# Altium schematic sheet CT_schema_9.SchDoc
size 287 x 160 mm
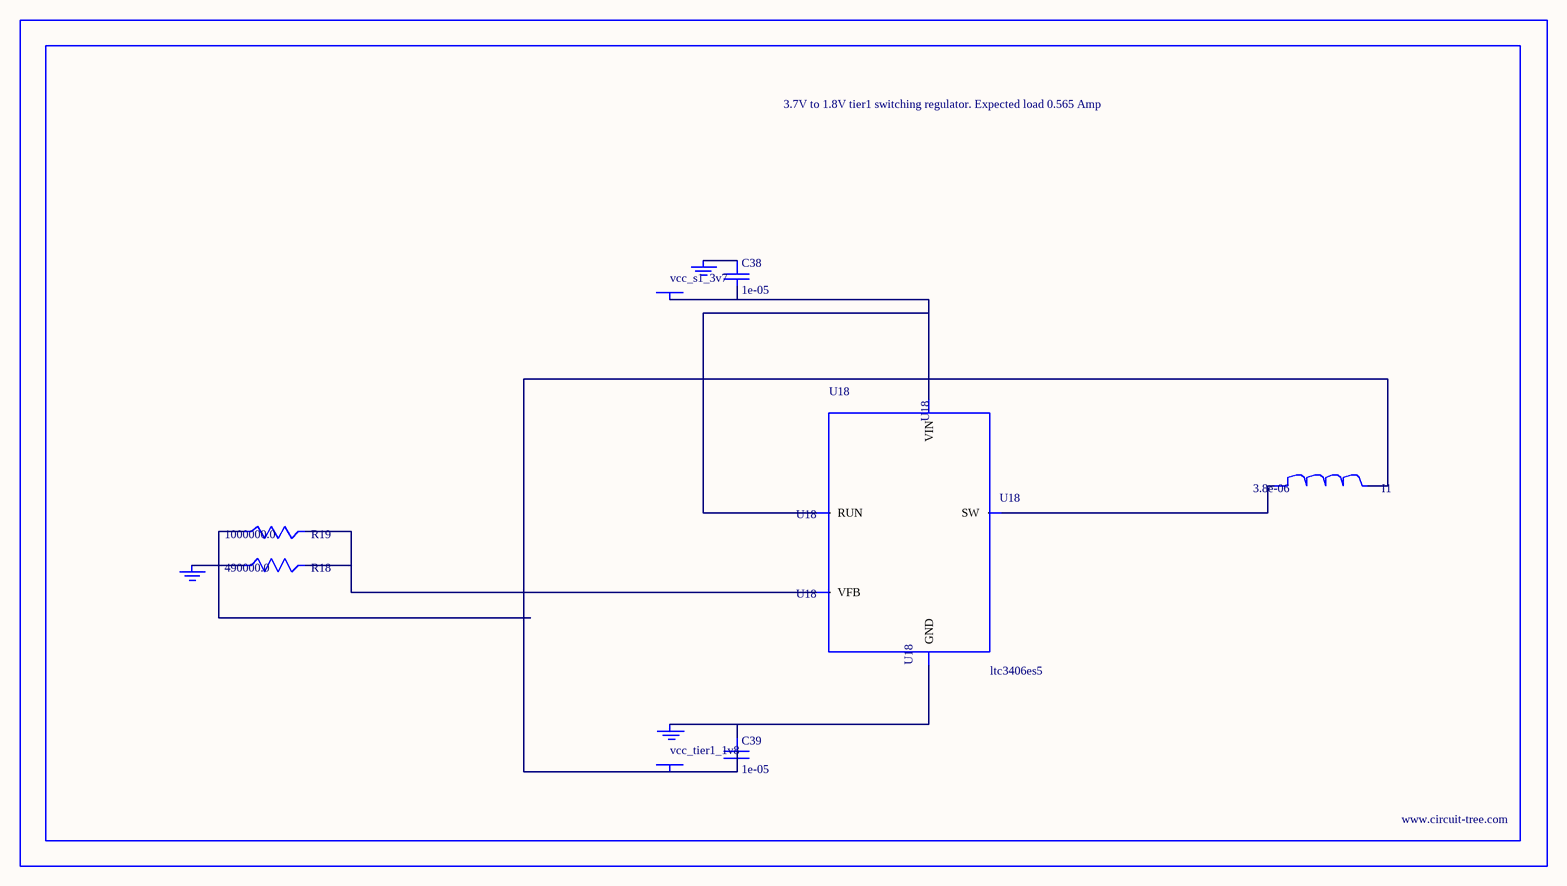
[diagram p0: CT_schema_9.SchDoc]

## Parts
BORDER8  (no value)
C38  1e-05  [C0805]
C39  1e-05  [C0805]
GND_INSTANCE_8_0  (no value)
GND_INSTANCE_8_1  (no value)
GND_INSTANCE_8_2  (no value)
I1  3.8e-06  [DR1040]
POWER_INSTANCE_8_0  vcc_tier1_1v8
POWER_INSTANCE_8_1  vcc_s1_3v7
R18  490000.0  [R0603]
R19  1000000.0  [R0603]
U18  ltc3406es5  [TSOT-23-5]

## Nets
NetC38_1: C38.1 GND_INSTANCE_8_1.0(GND)
NetC38_2: C38.2 POWER_INSTANCE_8_1.0(PWR) U18.1(RUN) U18.4(VIN)
NetC39_1: C39.1 GND_INSTANCE_8_0.0(GND) U18.2(GND)
NetC39_2: C39.2 I1.2 POWER_INSTANCE_8_0.0(PWR) R19.1
NetGND_INSTANCE_8_2_0: GND_INSTANCE_8_2.0(GND) R18.1
NetI1_1: I1.1 U18.3(SW)
NetR18_2: R18.2 R19.2 U18.5(VFB)

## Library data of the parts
BORDER8 = BORDER_PAGE8
C38 C39 = C0805C106K8RACTU
GND_INSTANCE_8_0-GND_INSTANCE_8_2 = GND
I1 = DR1040-3R8-R
POWER_INSTANCE_8_0 POWER_INSTANCE_8_1 = PWR
R18 = R18
R19 = RC0603JR-071ML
